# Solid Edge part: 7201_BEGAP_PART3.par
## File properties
Author: PARTuser1
Template: Normal.par
Last saved by: Francesco
Revision: 3
Application: Solid Edge
Material: Acciaio
Stile della faccia: Acciaio
Stile di riempimento: ANSI32(Acciaio)
Stile virtuale: Acciaio lavorato a macchina
Coef. of Thermal Exp: 0.0
Thermal Conductivity: 32.0
Specific Heat: 481.0
Modulus of Elasticity: 199947953000.0
Poisson's Ratio: 0.29
Yield Stress: 262000766.0
Ultimate Stress: 358527364.0
Elongation: 0.0
Tipo di contenuto documento: 0
Density: 7833,000 kg/m^3
Accuracy: 0,990
CADENASNORM: 7201 BEGAP_PART3
CADENAS_NB: 7201 BEGAP_PART3
CADENAS_NN: _PART3
CADENAS_NBSYN: 7201 BEGAP_PART3
CADENAS_LINA: 7201 BEGAP_PART3
CADENAS_Z: 10.000
CADENAS_Y0W2: 10.604
CADENAS_XIP: 0.000
CADENAS_XIN: 0.000
CADENAS_YIAC: 10.100
CADENAS_HIAC: 4.100
CADENAS_BEAC: 10.000
CADENAS_HI1: 2.250
CADENAS_R2I: 0.200
CADENAS_RWB: 3.000
CADENAS_XEP: 0.000
CADENAS_R2E: 0.100
CADENAS_Z0W2: 3.446
CADENAS_XEN: 0.000
CADENAS_RI: 3.000
CADENAS_X0WB: 5.000
CADENAS_RE: 3.000
CADENAS_C1E: 0.000
CADENAS_HE2: -16.000
CADENAS_HE1: 1.900
CADENAS_YEAC: 12.550
CADENAS_HEAC: 3.450
CADENAS_X0W2: 5.000
CADENAS_BOREDIAMETER: 12.000
CADENAS_BIAC: 10.000
CADENAS_BCH: 0.000
CADENAS_R1I: 0.600
CADENAS_PRODUCTID: 1210023201.000
CADENAS_BEARINGWIDTH: 10.000
CADENAS_R1E: 0.300
CADENAS_Y0WE: 11.150
CADENAS_Y0WB: 11.150
CADENAS_X0IP: 5.000
CADENAS_Y0IAC: 11.150
CADENAS_comment: design:acbb1; version:5000.3; lang:it; selectedUnitParts:000000; action:download; skf2d3daction.jsp version:2008-03-06; getRequestURI:/skf/skf3dnew/skf2d3daction.jsp
CADENAS_KT: DUMMY
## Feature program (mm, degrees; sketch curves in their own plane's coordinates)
sketch for "unnamed RevolvedProtrusion 1" plane through (0, 0, 0) normal (0, 0, 1) x-axis (1, 0, 0)
  arc centre (5, 11.15) radius 3 from (2, 11.15) to (8, 11.15) cw
  line (8, 11.15) -> (2, 11.15)
revolve "unnamed RevolvedProtrusion 1" add finite 360 deg about sketch line (50, 11.15) -> (-50, 11.15)
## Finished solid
Body 1: solid body, 1 face, 0 edges, 0 vertices.
  Faces by surface: sphere 1
Spherical faces by radius (mm): R3 x1
